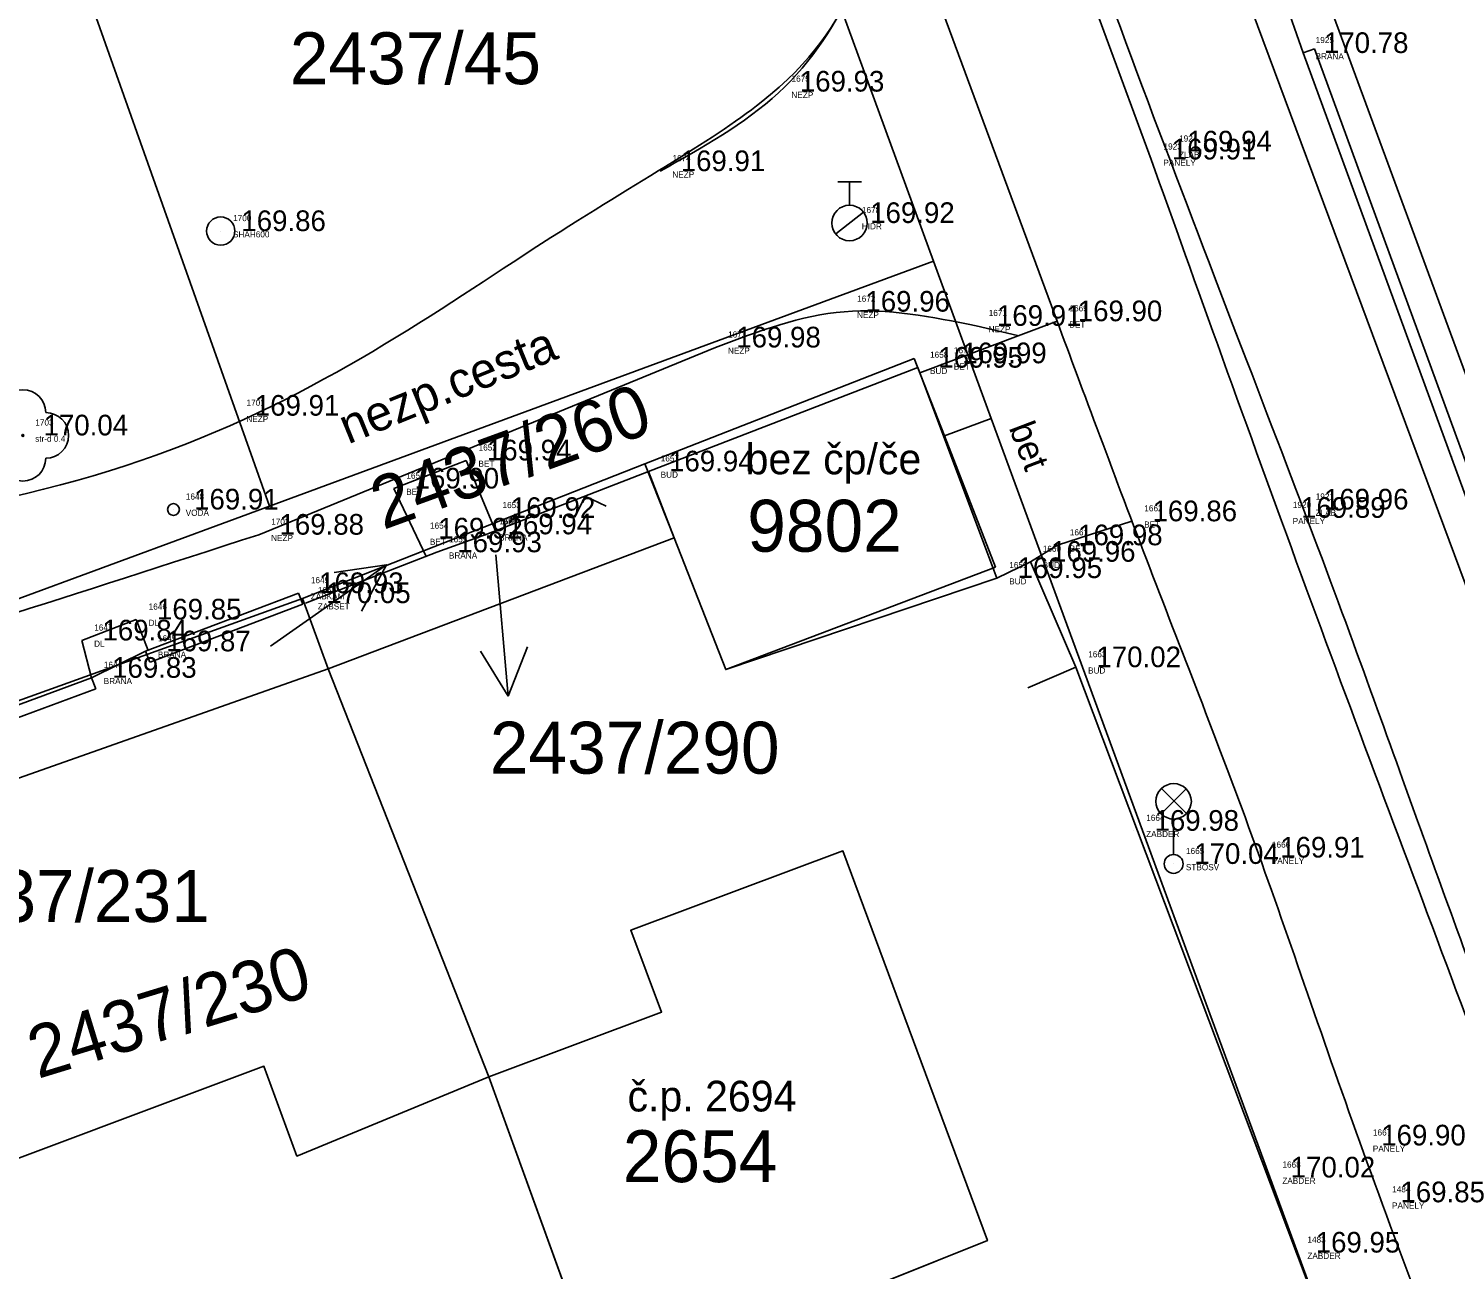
# Model space of a CAD drawing. Extents: x -566117 to -565580, y -1202428 to -1201938.
# Drawn here: x -565922.24 to -565892.03, y -1202128.54 to -1202102.26 of the extents above; entities that cross this region are included whole.
import ezdxf

# ---------------------------------------------------------------- set-up
doc = ezdxf.new("R2010")
doc.units = 0
for name, color, linetype in [('1029', 7, 'Continuous'), ('Bod', 7, 'Continuous'), ('BUDOVY_MĚŘ (Construction)', 7, 'Continuous'), ('BUOVY_NEMĚŘ', 7, 'Continuous'), ('CIZÍ_NADZEM', 7, 'Continuous'), ('Implicitní', 7, 'Continuous'), ('Kanalizace', 7, 'Continuous'), ('Katastr', 7, 'Continuous'), ('Kod', 7, 'Continuous'), ('Oplocení', 7, 'Continuous'), ('POMOC_POPIS', 7, 'Continuous'), ('Voda', 7, 'Continuous'), ('Výška', 7, 'Continuous'), ('ZELEŇ', 7, 'Continuous'), ('Zpevněné plohy', 7, 'Continuous'), ('Číslo', 7, 'Continuous'), ('Číslo popisné', 7, 'Continuous')]:
    doc.layers.add(name, color=color, linetype=linetype)

# ---------------------------------------------------------------- blocks, each defined once
blk = doc.blocks.new('1029$2')
at = {"layer": 'Katastr'}
for p, q in [((0, 3.001), (-0.501, 2)), ((0, 0), (0, 3.001)), ((0, 3.001), (0.501, 2))]:
    blk.add_line(p, q, dxfattribs=at)
blk = doc.blocks.new('A$C69D74C1E')
at = {"layer": 'Katastr'}
for p, q in [((181.01, -66.83), (149.9, 16.82)), ((182.39, -66.32), (165.44, -20.31)), ((161.85, -38.75), (156.46, -24.01)), ((147.79, -43.94), (142.52, -29.09)), ((147.79, -43.94), (161.85, -38.75)), ((161.85, -38.75), (163.07, -42.08)), ((155.74, -43.04), (161.44, -40.81)), ((161.44, -40.81), (162.08, -42.45)), ((162.08, -42.45), (163.07, -42.08)), ((163.07, -42.08), (171.53, -65.1)), ((162.08, -42.45), (163.16, -45.23)), ((148.49, -45.89), (155.74, -43.04)), ((155.74, -43.04), (156.36, -44.61)), ((156.36, -44.61), (149.03, -47.38)), ((157.45, -47.4), (156.36, -44.61)), ((163.16, -45.23), (157.45, -47.4)), ((138.19, -49.6), (148.49, -45.89)), ((149.03, -47.38), (148.49, -45.89)), ((149.03, -47.38), (138.74, -51.02)), ((149.03, -47.38), (152.43, -56.02)), ((159.93, -51.24), (162.99, -59.49)), ((154.87, -62.74), (152.43, -56.02)), ((162.99, -59.49), (154.87, -62.74))]:
    blk.add_line(p, q, dxfattribs=at)
for points in [[(128.45, -34.52), (133.85, -49.08), (147.79, -43.94)], [(152.43, -56.02), (156.09, -54.65), (155.44, -52.92), (159.93, -51.24)], [(152.43, -56.02), (148.37, -57.7), (147.67, -55.8), (140.57, -58.46)]]:
    blk.add_lwpolyline(points, dxfattribs=at)
at = {"layer": '1029'}
for p, rotation in [((147.81, -46.9), -55), ((152.58, -44.97), -175.00000000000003)]:
    blk.add_blockref('1029$2', p, dxfattribs=dict(at, rotation=rotation))
at = {"layer": 'Katastr'}
for s, p in [('2437/45', (148.22, -35.003)), ('9802', (157.905, -44.903)), ('2437/290', (152.455, -49.603)), ('2437/231', (140.39, -52.743)), ('2654', (155.27, -58.253))]:
    blk.add_text(s, height=1.1, dxfattribs=at).set_placement(p)
for s, rotation, p in [('2437/260', 20, (150.195, -44.445)), ('2437/230', 17, (142.883, -56.069))]:
    blk.add_text(s, height=1.1, rotation=rotation, dxfattribs=at).set_placement(p)
blk = doc.blocks.new('POINT_DISPLAY')
at = {"layer": 'Implicitní'}
blk.add_line((0, 0), (0, 0), dxfattribs=at)
blk = doc.blocks.new('3$13')
at = {"layer": 'ZELEŇ'}
blk.add_circle((0, 0), 0.02, dxfattribs=at)
for centre, start, end in [((0.000055, 0.484), 0, 179.9999972), ((-0.483945, 0), 90, 269.9999972), ((0.484055, 0), 270, 89.9999972), ((0.000055, -0.484), 180.0000028, 0)]:
    blk.add_arc(centre, 0.484, start, end, dxfattribs=at)
blk.add_blockref('POINT_DISPLAY', (0, 0), dxfattribs=at)
blk = doc.blocks.new('6.560')
at = {"layer": 'CIZÍ_NADZEM'}
for p, q in [((-0.528, 2.124), (0.528, 3.18)), ((0.544, 2.13), (-0.512, 3.188)), ((0, 1.9), (0, 0.4))]:
    blk.add_line(p, q, dxfattribs=at)
for centre, radius in [((0, 2.65), 0.75), ((0, 0), 0.4)]:
    blk.add_circle(centre, radius, dxfattribs=at)
blk = doc.blocks.new('6.130')
at = {"layer": 'Voda'}
for p, q in [((-0.5, 1.75), (0.5, 1.75)), ((0, 0.75), (0, 1.75)), ((-0.588, -0.462), (0.592, 0.464))]:
    blk.add_line(p, q, dxfattribs=at)
blk.add_circle((0, 0), 0.75, dxfattribs=at)

msp = doc.modelspace()

# ---------------------------------------------------------------- linework, layer by layer
at = {"layer": 'BUDOVY_MĚŘ (Construction)'}
for p, q in [((-565909.118, -1202111.642), (-565903.415, -1202109.445)), ((-565903.415, -1202109.445), (-565901.737, -1202113.901)), ((-565909.118, -1202111.642), (-565908.57, -1202113.05)), ((-565901.028, -1202113.555), (-565901.737, -1202113.901)), ((-565901.028, -1202113.555), (-565900.067, -1202115.788)), ((-565900.067, -1202115.788), (-565901.081, -1202116.225))]:
    msp.add_line(p, q, dxfattribs=at)
at = {"layer": 'BUOVY_NEMĚŘ'}
for points in [[(-565908.57, -1202113.05), (-565907.48, -1202115.84), (-565901.737, -1202113.901)], [(-565912.5, -1202124.46), (-565908.84, -1202123.09), (-565909.49, -1202121.36), (-565905, -1202119.68), (-565901.94, -1202127.93), (-565910.06, -1202131.18), (-565921.24, -1202135.22), (-565924.08, -1202136.25), (-565927.21, -1202127.96), (-565924.36, -1202126.9), (-565917.26, -1202124.24), (-565916.56, -1202126.14), (-565912.5, -1202124.46), (-565910.06, -1202131.18)]]:
    msp.add_lwpolyline(points, dxfattribs=at)
at = {"layer": 'Implicitní'}
for p, q in [((-565902.174, -1202108.56), (-565901.301, -1202108.767)), ((-565917.367, -1202112.982), (-565907.694, -1202109.017))]:
    msp.add_line(p, q, dxfattribs=at)
for points in [[(-565932.951, -1202113.731), (-565927.736, -1202113.122), (-565919.003, -1202112.101), (-565911.071, -1202106.443), (-565906.177, -1202103.795), (-565904.581, -1202101.314), (-565904.179, -1202099.548), (-565904.004, -1202098.78)], [(-565908.87, -1202105.284), (-565907.977, -1202104.787), (-565906.181, -1202103.788), (-565904.581, -1202101.315), (-565904.179, -1202099.549), (-565904.004, -1202098.78)], [(-565902.174, -1202108.56), (-565903.109, -1202108.373), (-565904.992, -1202107.996), (-565906.789, -1202108.675), (-565907.694, -1202109.017)], [(-565950.101, -1202120.824), (-565947.147, -1202120.442), (-565935.99, -1202119.001), (-565925.258, -1202115.532), (-565917.367, -1202112.982)]]:
    msp.add_open_spline(points, degree=3, dxfattribs=at)
at = {"layer": 'Kanalizace'}
msp.add_circle((-565918.174, -1202106.553), 0.3, dxfattribs=at)
at = {"layer": 'Oplocení'}
for p, q in [((-565895.25, -1202102.782), (-565896.333, -1202099.716)), ((-565895.25, -1202102.782), (-565895.015, -1202102.696)), ((-565888.244, -1202121.919), (-565895.25, -1202102.782)), ((-565895.015, -1202102.696), (-565888.009, -1202121.833)), ((-565912.538, -1202112.974), (-565909.118, -1202111.642)), ((-565913.601, -1202113.354), (-565912.538, -1202112.974)), ((-565916.379, -1202114.431), (-565913.601, -1202113.354)), ((-565919.766, -1202115.452), (-565916.528, -1202114.219)), ((-565916.528, -1202114.219), (-565916.434, -1202114.45)), ((-565919.672, -1202115.684), (-565916.434, -1202114.45)), ((-565920.912, -1202116.012), (-565919.766, -1202115.452)), ((-565919.766, -1202115.452), (-565919.677, -1202115.685)), ((-565893.349, -1202133.598), (-565900.067, -1202115.788)), ((-565926.624, -1202118.126), (-565920.912, -1202116.012)), ((-565920.912, -1202116.012), (-565920.818, -1202116.244)), ((-565920.818, -1202116.244), (-565926.531, -1202118.357))]:
    msp.add_line(p, q, dxfattribs=at)
msp.add_lwpolyline([(-565910.674, -1202112.609), (-565910.458, -1202112.164), (-565910.013, -1202112.38)], dxfattribs=at)
at = {"layer": 'Voda'}
msp.add_circle((-565919.175, -1202112.449), 0.125, dxfattribs=at)
at = {"layer": 'Zpevněné plohy'}
for p, q in [((-565908.642, -1202086.351), (-565900.462, -1202108.462)), ((-565903.134, -1202092.404), (-565898.471, -1202105.036)), ((-565903.373, -1202109.558), (-565900.462, -1202108.462)), ((-565914.505, -1202112.005), (-565912.976, -1202111.409)), ((-565912.976, -1202111.409), (-565912.355, -1202112.903)), ((-565914.505, -1202112.005), (-565913.826, -1202113.441)), ((-565900.456, -1202113.206), (-565898.878, -1202112.698)), ((-565900.456, -1202113.206), (-565901.028, -1202113.555)), ((-565921.116, -1202115.222), (-565919.962, -1202114.778)), ((-565919.962, -1202114.778), (-565919.713, -1202115.432)), ((-565921.116, -1202115.222), (-565920.912, -1202116.012))]:
    msp.add_line(p, q, dxfattribs=at)
for points in [[(-565891.477, -1202122.761), (-565891.53, -1202122.617), (-565892.789, -1202119.18), (-565894.921, -1202113.182), (-565898.82, -1202103.223), (-565901.226, -1202096.449), (-565902.726, -1202092.224)], [(-565885.905, -1202138.743), (-565886.915, -1202136.146), (-565888.781, -1202131.346), (-565892.004, -1202122.62), (-565895.258, -1202114.009), (-565897.564, -1202107.568), (-565898.471, -1202105.036)], [(-565870.836, -1202187.735), (-565871.649, -1202185.484), (-565873.23, -1202181.104), (-565875.832, -1202174.081), (-565878.484, -1202166.972), (-565882.365, -1202157.37), (-565885.162, -1202149.181), (-565888.939, -1202140.01), (-565891.203, -1202133.383), (-565894.098, -1202125.895), (-565896.244, -1202119.433), (-565898.532, -1202113.67), (-565899.938, -1202109.875), (-565900.462, -1202108.462)]]:
    msp.add_open_spline(points, degree=3, dxfattribs=at)

# ---------------------------------------------------------------- block references
at = {"layer": 'Bod'}
for p in [(-565895.25, -1202102.782), (-565906.349, -1202103.599), (-565898.141, -1202104.867), (-565898.471, -1202105.036), (-565908.87, -1202105.284), (-565904.858, -1202106.382), (-565918.174, -1202106.553), (-565904.959, -1202108.259), (-565900.462, -1202108.462), (-565902.174, -1202108.56), (-565907.694, -1202109.017), (-565903.415, -1202109.445), (-565902.911, -1202109.352), (-565917.89, -1202110.462), (-565912.976, -1202111.409), (-565892.089, -1202111.324), (-565909.118, -1202111.642), (-565914.505, -1202112.005), (-565919.175, -1202112.449), (-565895.248, -1202112.449), (-565912.469, -1202112.628), (-565898.878, -1202112.698), (-565895.734, -1202112.625), (-565917.367, -1202112.982), (-565914.005, -1202113.063), (-565912.538, -1202112.974), (-565913.601, -1202113.354), (-565900.456, -1202113.206), (-565901.028, -1202113.555), (-565901.737, -1202113.901), (-565916.528, -1202114.219), (-565916.379, -1202114.431), (-565919.962, -1202114.778), (-565921.116, -1202115.222), (-565919.766, -1202115.452), (-565900.067, -1202115.788), (-565920.912, -1202116.012), (-565898.838, -1202119.252), (-565897.995, -1202119.954), (-565896.175, -1202119.819), (-565894.036, -1202125.915), (-565895.954, -1202126.594), (-565893.63, -1202127.119), (-565895.424, -1202128.184)]:
    msp.add_blockref('POINT_DISPLAY', p, dxfattribs=at)
at = {"layer": 'CIZÍ_NADZEM', "xscale": 0.5, "yscale": 0.5}
for name, p in [('6.130', (-565904.858, -1202106.382)), ('6.560', (-565897.995, -1202119.954))]:
    msp.add_blockref(name, p, dxfattribs=at)
at = {"layer": 'Implicitní'}
msp.add_blockref('A$C69D74C1E', (-566064.93, -1202068.44), dxfattribs=at)
at = {"layer": 'ZELEŇ'}
msp.add_blockref('3$13', (-565922.364, -1202110.88), dxfattribs=at)

# ---------------------------------------------------------------- texts
at = {"layer": 'Kod'}
for s, p in [('BRANA', (-565894.99, -1202102.916)), ('NEZP', (-565906.089, -1202103.734)), ('ZLAB', (-565897.882, -1202105.002)), ('PANELY', (-565898.212, -1202105.171)), ('NEZP', (-565908.611, -1202105.419)), ('HIDR', (-565904.599, -1202106.516)), ('SHAH600', (-565917.915, -1202106.687)), ('NEZP', (-565904.7, -1202108.393)), ('BET', (-565900.203, -1202108.597)), ('NEZP', (-565901.914, -1202108.695)), ('NEZP', (-565907.434, -1202109.151)), ('BET', (-565902.651, -1202109.486)), ('BUD', (-565903.155, -1202109.58)), ('NEZP', (-565917.631, -1202110.596)), ('str-d 0.4', (-565922.104, -1202111.015)), ('BET', (-565912.716, -1202111.544)), ('BUD', (-565908.858, -1202111.776)), ('BET', (-565914.246, -1202112.139)), ('VODA', (-565918.916, -1202112.583)), ('ZLAB', (-565894.989, -1202112.583)), ('BET', (-565912.21, -1202112.763)), ('BET', (-565898.619, -1202112.832)), ('PANELY', (-565895.474, -1202112.759)), ('NEZP', (-565917.108, -1202113.116)), ('BET', (-565913.745, -1202113.198)), ('BRANA', (-565912.278, -1202113.108)), ('BRANA', (-565913.342, -1202113.488)), ('BET', (-565900.196, -1202113.341)), ('BUD', (-565900.769, -1202113.69)), ('BUD', (-565901.478, -1202114.035)), ('ZABKAM', (-565916.268, -1202114.353)), ('ZABSET', (-565916.119, -1202114.566)), ('DL', (-565919.702, -1202114.913)), ('DL', (-565920.856, -1202115.356)), ('BRANA', (-565919.506, -1202115.586)), ('BUD', (-565899.807, -1202115.923)), ('BRANA', (-565920.652, -1202116.146)), ('ZABDER', (-565898.578, -1202119.386)), ('STBOSV', (-565897.736, -1202120.088)), ('PANELY', (-565895.916, -1202119.954)), ('PANELY', (-565893.777, -1202126.049)), ('ZABDER', (-565895.694, -1202126.729)), ('PANELY', (-565893.37, -1202127.253)), ('ZABDER', (-565895.164, -1202128.318))]:
    msp.add_text(s, height=0.13, dxfattribs=at).set_placement(p)
at = {"layer": 'POMOC_POPIS'}
for s, height, rotation, p in [('nezp.cesta', 0.75, 22.216, (-565915.478, -1202111.073)), ('bet', 0.55, 290.8271, (-565901.49, -1202110.716))]:
    msp.add_text(s, height=height, rotation=rotation, dxfattribs=at).set_placement(p)
at = {"layer": 'Výška'}
for s, p in [('170.78', (-565894.812, -1202102.782)), ('169.93', (-565905.911, -1202103.599)), ('169.91', (-565898.034, -1202105.036)), ('169.94', (-565897.704, -1202104.867)), ('169.91', (-565908.433, -1202105.284)), ('169.86', (-565917.737, -1202106.553)), ('169.92', (-565904.421, -1202106.382)), ('169.96', (-565904.522, -1202108.259)), ('169.91', (-565901.736, -1202108.56)), ('169.90', (-565900.025, -1202108.462)), ('169.98', (-565907.256, -1202109.017)), ('169.95', (-565902.977, -1202109.445)), ('169.99', (-565902.473, -1202109.352)), ('169.91', (-565917.453, -1202110.462)), ('170.04', (-565921.926, -1202110.88)), ('169.94', (-565912.538, -1202111.409)), ('169.94', (-565908.68, -1202111.642)), ('169.90', (-565914.068, -1202112.005)), ('169.91', (-565918.738, -1202112.449)), ('169.96', (-565894.811, -1202112.449)), ('169.92', (-565912.032, -1202112.628)), ('169.86', (-565898.441, -1202112.698)), ('169.89', (-565895.296, -1202112.625)), ('169.88', (-565916.93, -1202112.982)), ('169.92', (-565913.567, -1202113.063)), ('169.94', (-565912.1, -1202112.974)), ('169.98', (-565900.018, -1202113.206)), ('169.93', (-565913.164, -1202113.354)), ('169.96', (-565900.591, -1202113.555)), ('169.95', (-565901.3, -1202113.901)), ('169.93', (-565916.09, -1202114.219)), ('170.05', (-565915.941, -1202114.431)), ('169.85', (-565919.524, -1202114.778)), ('169.84', (-565920.678, -1202115.222)), ('169.87', (-565919.328, -1202115.452)), ('170.02', (-565899.629, -1202115.788)), ('169.83', (-565920.474, -1202116.012)), ('169.98', (-565898.4, -1202119.252)), ('169.91', (-565895.738, -1202119.819)), ('170.04', (-565897.558, -1202119.954)), ('169.90', (-565893.599, -1202125.915)), ('170.02', (-565895.516, -1202126.594)), ('169.85', (-565893.192, -1202127.119)), ('169.95', (-565894.986, -1202128.184))]:
    msp.add_text(s, height=0.4375, dxfattribs=at).set_placement(p)
at = {"layer": 'Číslo'}
for s, p in [('1925', (-565894.987, -1202102.572)), ('1675', (-565906.087, -1202103.39)), ('1924', (-565897.879, -1202104.658)), ('1923', (-565898.209, -1202104.827)), ('1674', (-565908.608, -1202105.075)), ('1678', (-565904.596, -1202106.172)), ('1700', (-565917.912, -1202106.343)), ('1672', (-565904.697, -1202108.049)), ('1671', (-565901.911, -1202108.351)), ('1669', (-565900.2, -1202108.253)), ('1673', (-565907.431, -1202108.807)), ('1658', (-565903.153, -1202109.236)), ('1670', (-565902.648, -1202109.142)), ('1701', (-565917.628, -1202110.252)), ('1703', (-565922.101, -1202110.671)), ('1652', (-565912.713, -1202111.2)), ('1657', (-565908.856, -1202111.432)), ('1651', (-565914.243, -1202111.795)), ('1648', (-565918.913, -1202112.239)), ('1921', (-565894.986, -1202112.239)), ('1653', (-565912.207, -1202112.419)), ('1662', (-565898.616, -1202112.488)), ('1920', (-565895.471, -1202112.415)), ('1702', (-565917.105, -1202112.772)), ('1654', (-565913.742, -1202112.854)), ('1656', (-565912.275, -1202112.764)), ('1655', (-565913.339, -1202113.144)), ('1661', (-565900.193, -1202112.997)), ('1660', (-565900.766, -1202113.346)), ('1659', (-565901.475, -1202113.691)), ('1649', (-565916.265, -1202114.009)), ('1650', (-565916.116, -1202114.222)), ('1646', (-565919.7, -1202114.569)), ('1647', (-565920.853, -1202115.013)), ('1645', (-565919.503, -1202115.242)), ('1663', (-565899.804, -1202115.579)), ('1644', (-565920.649, -1202115.802)), ('1664', (-565898.575, -1202119.042)), ('1665', (-565897.733, -1202119.744)), ('1666', (-565895.913, -1202119.61)), ('1667', (-565893.774, -1202125.705)), ('1668', (-565895.691, -1202126.385)), ('1484', (-565893.367, -1202126.909)), ('1483', (-565895.162, -1202127.974))]:
    msp.add_text(s, height=0.13, dxfattribs=at).set_placement(p)
at = {"layer": 'Číslo popisné'}
for s, p in [('bez čp/če', (-565907.059, -1202111.703)), ('č.p. 2694', (-565909.56, -1202125.196))]:
    msp.add_text(s, height=0.65, dxfattribs=at).set_placement(p)

doc.saveas('drawing.dxf')
